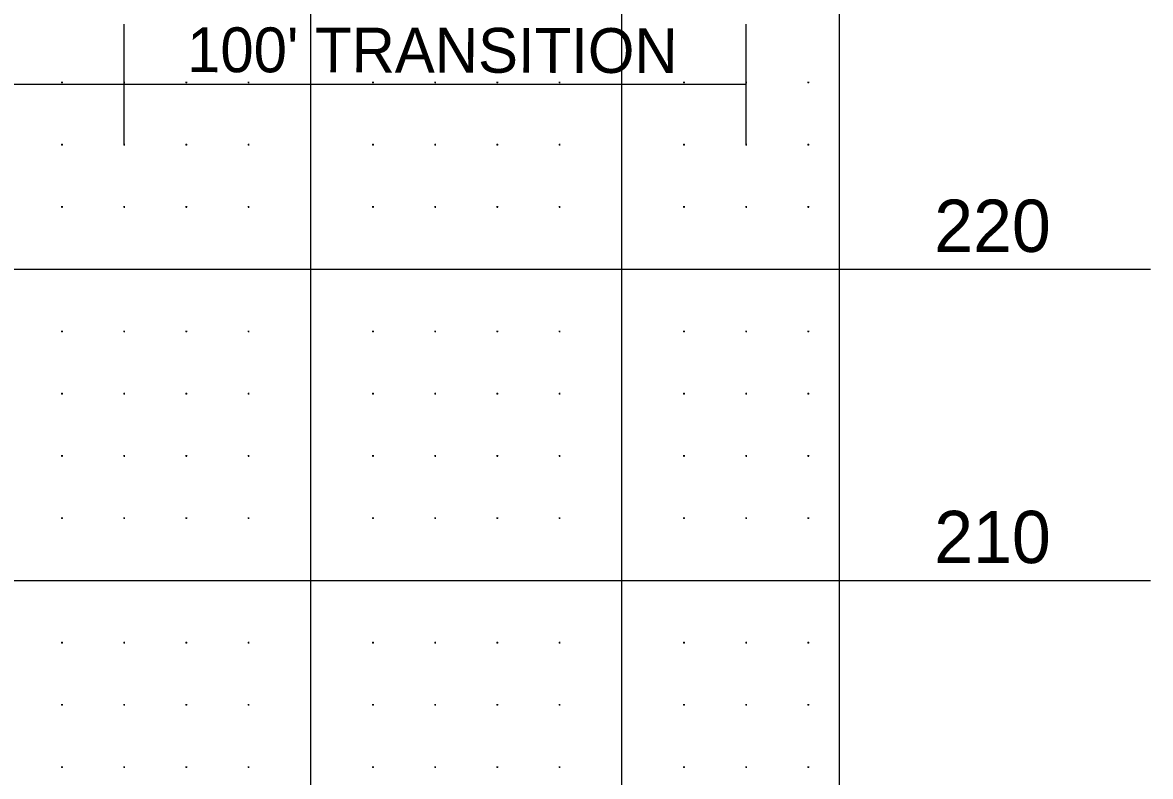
# Model space of a CAD drawing. Extents: x 471 to 2121, y 140 to 650.
# Drawn here: x 1939.7 to 2121.1, y 418.5 to 539.6 of the extents above; entities that cross this region are included whole.
import ezdxf

# ---------------------------------------------------------------- set-up
doc = ezdxf.new("R2010")
doc.units = 0
for name, color, linetype in [('DSN_DRFT_Border Grid', 7, 'Continuous'), ('DSN_RDWY_Prof Annotation', 7, 'Continuous'), ('Transition Dimensions', 7, 'Continuous')]:
    doc.layers.add(name, color=color, linetype=linetype)

msp = doc.modelspace()

# ---------------------------------------------------------------- linework, layer by layer
at = {"layer": 'DSN_DRFT_Border Grid'}
for p, q in [((1986.06, 150), (1986.06, 650)), ((1986.06, 150), (1986.06, 650)), ((2036.06, 150), (2036.06, 650)), ((2036.06, 150), (2036.06, 650)), ((2071.06, 150), (2071.06, 650)), ((2071.06, 150), (2071.06, 650)), ((1946.18, 530), (1945.94, 530)), ((1946.18, 530), (1945.94, 530)), ((1946.06, 530.12), (1946.06, 529.88)), ((1946.06, 530.12), (1946.06, 529.88)), ((1956.18, 530), (1955.94, 530)), ((1956.18, 530), (1955.94, 530)), ((1956.06, 530.12), (1956.06, 529.88)), ((1956.06, 530.12), (1956.06, 529.88)), ((1966.18, 530), (1965.94, 530)), ((1966.18, 530), (1965.94, 530)), ((1966.06, 530.12), (1966.06, 529.88)), ((1966.06, 530.12), (1966.06, 529.88)), ((1976.18, 530), (1975.94, 530)), ((1976.18, 530), (1975.94, 530)), ((1976.06, 530.12), (1976.06, 529.88)), ((1976.06, 530.12), (1976.06, 529.88)), ((1996.18, 530), (1995.94, 530)), ((1996.18, 530), (1995.94, 530)), ((1996.06, 530.12), (1996.06, 529.88)), ((1996.06, 530.12), (1996.06, 529.88)), ((2006.18, 530), (2005.94, 530)), ((2006.18, 530), (2005.94, 530)), ((2006.06, 530.12), (2006.06, 529.88)), ((2006.06, 530.12), (2006.06, 529.88)), ((2016.18, 530), (2015.94, 530)), ((2016.18, 530), (2015.94, 530)), ((2016.06, 530.12), (2016.06, 529.88)), ((2016.06, 530.12), (2016.06, 529.88)), ((2026.18, 530), (2025.94, 530)), ((2026.18, 530), (2025.94, 530)), ((2026.06, 530.12), (2026.06, 529.88)), ((2026.06, 530.12), (2026.06, 529.88)), ((2046.18, 530), (2045.94, 530)), ((2046.18, 530), (2045.94, 530)), ((2046.06, 530.12), (2046.06, 529.88)), ((2046.06, 530.12), (2046.06, 529.88)), ((2056.18, 530), (2055.94, 530)), ((2056.18, 530), (2055.94, 530)), ((2056.06, 530.12), (2056.06, 529.88)), ((2056.06, 530.12), (2056.06, 529.88)), ((2066.18, 530), (2065.94, 530)), ((2066.18, 530), (2065.94, 530)), ((2066.06, 530.12), (2066.06, 529.88)), ((2066.06, 530.12), (2066.06, 529.88)), ((1946.18, 520), (1945.94, 520)), ((1946.18, 520), (1945.94, 520)), ((1946.06, 520.12), (1946.06, 519.88)), ((1946.06, 520.12), (1946.06, 519.88)), ((1956.18, 520), (1955.94, 520)), ((1956.18, 520), (1955.94, 520)), ((1956.06, 520.12), (1956.06, 519.88)), ((1956.06, 520.12), (1956.06, 519.88)), ((1966.18, 520), (1965.94, 520)), ((1966.18, 520), (1965.94, 520)), ((1966.06, 520.12), (1966.06, 519.88)), ((1966.06, 520.12), (1966.06, 519.88)), ((1976.18, 520), (1975.94, 520)), ((1976.18, 520), (1975.94, 520)), ((1976.06, 520.12), (1976.06, 519.88)), ((1976.06, 520.12), (1976.06, 519.88)), ((1996.18, 520), (1995.94, 520)), ((1996.18, 520), (1995.94, 520)), ((1996.06, 520.12), (1996.06, 519.88)), ((1996.06, 520.12), (1996.06, 519.88)), ((2006.18, 520), (2005.94, 520)), ((2006.18, 520), (2005.94, 520)), ((2006.06, 520.12), (2006.06, 519.88)), ((2006.06, 520.12), (2006.06, 519.88)), ((2016.18, 520), (2015.94, 520)), ((2016.18, 520), (2015.94, 520)), ((2016.06, 520.12), (2016.06, 519.88)), ((2016.06, 520.12), (2016.06, 519.88)), ((2026.18, 520), (2025.94, 520)), ((2026.18, 520), (2025.94, 520)), ((2026.06, 520.12), (2026.06, 519.88)), ((2026.06, 520.12), (2026.06, 519.88)), ((2046.18, 520), (2045.94, 520)), ((2046.18, 520), (2045.94, 520)), ((2046.06, 520.12), (2046.06, 519.88)), ((2046.06, 520.12), (2046.06, 519.88)), ((2056.18, 520), (2055.94, 520)), ((2056.18, 520), (2055.94, 520)), ((2056.06, 520.12), (2056.06, 519.88)), ((2056.06, 520.12), (2056.06, 519.88)), ((2066.18, 520), (2065.94, 520)), ((2066.18, 520), (2065.94, 520)), ((2066.06, 520.12), (2066.06, 519.88)), ((2066.06, 520.12), (2066.06, 519.88)), ((1946.18, 510), (1945.94, 510)), ((1946.18, 510), (1945.94, 510)), ((1946.06, 510.12), (1946.06, 509.88)), ((1946.06, 510.12), (1946.06, 509.88)), ((1956.18, 510), (1955.94, 510)), ((1956.18, 510), (1955.94, 510)), ((1956.06, 510.12), (1956.06, 509.88)), ((1956.06, 510.12), (1956.06, 509.88)), ((1966.18, 510), (1965.94, 510)), ((1966.18, 510), (1965.94, 510)), ((1966.06, 510.12), (1966.06, 509.88)), ((1966.06, 510.12), (1966.06, 509.88)), ((1976.18, 510), (1975.94, 510)), ((1976.18, 510), (1975.94, 510)), ((1976.06, 510.12), (1976.06, 509.88)), ((1976.06, 510.12), (1976.06, 509.88)), ((1996.18, 510), (1995.94, 510)), ((1996.18, 510), (1995.94, 510)), ((1996.06, 510.12), (1996.06, 509.88)), ((1996.06, 510.12), (1996.06, 509.88)), ((2006.18, 510), (2005.94, 510)), ((2006.18, 510), (2005.94, 510)), ((2006.06, 510.12), (2006.06, 509.88)), ((2006.06, 510.12), (2006.06, 509.88)), ((2016.18, 510), (2015.94, 510)), ((2016.18, 510), (2015.94, 510)), ((2016.06, 510.12), (2016.06, 509.88)), ((2016.06, 510.12), (2016.06, 509.88)), ((2026.18, 510), (2025.94, 510)), ((2026.18, 510), (2025.94, 510)), ((2026.06, 510.12), (2026.06, 509.88)), ((2026.06, 510.12), (2026.06, 509.88)), ((2046.18, 510), (2045.94, 510)), ((2046.18, 510), (2045.94, 510)), ((2046.06, 510.12), (2046.06, 509.88)), ((2046.06, 510.12), (2046.06, 509.88)), ((2056.18, 510), (2055.94, 510)), ((2056.18, 510), (2055.94, 510)), ((2056.06, 510.12), (2056.06, 509.88)), ((2056.06, 510.12), (2056.06, 509.88)), ((2066.18, 510), (2065.94, 510)), ((2066.18, 510), (2065.94, 510)), ((2066.06, 510.12), (2066.06, 509.88)), ((2066.06, 510.12), (2066.06, 509.88)), ((521.06, 500), (2071.06, 500)), ((521.06, 500), (2071.06, 500)), ((2071.06, 500), (2121.06, 500)), ((1946.18, 490), (1945.94, 490)), ((1946.18, 490), (1945.94, 490)), ((1946.06, 490.12), (1946.06, 489.88)), ((1946.06, 490.12), (1946.06, 489.88)), ((1956.18, 490), (1955.94, 490)), ((1956.18, 490), (1955.94, 490)), ((1956.06, 490.12), (1956.06, 489.88)), ((1956.06, 490.12), (1956.06, 489.88)), ((1966.18, 490), (1965.94, 490)), ((1966.18, 490), (1965.94, 490)), ((1966.06, 490.12), (1966.06, 489.88)), ((1966.06, 490.12), (1966.06, 489.88)), ((1976.18, 490), (1975.94, 490)), ((1976.18, 490), (1975.94, 490)), ((1976.06, 490.12), (1976.06, 489.88)), ((1976.06, 490.12), (1976.06, 489.88)), ((1996.18, 490), (1995.94, 490)), ((1996.18, 490), (1995.94, 490)), ((1996.06, 490.12), (1996.06, 489.88)), ((1996.06, 490.12), (1996.06, 489.88)), ((2006.18, 490), (2005.94, 490)), ((2006.18, 490), (2005.94, 490)), ((2006.06, 490.12), (2006.06, 489.88)), ((2006.06, 490.12), (2006.06, 489.88)), ((2016.18, 490), (2015.94, 490)), ((2016.18, 490), (2015.94, 490)), ((2016.06, 490.12), (2016.06, 489.88)), ((2016.06, 490.12), (2016.06, 489.88)), ((2026.18, 490), (2025.94, 490)), ((2026.18, 490), (2025.94, 490)), ((2026.06, 490.12), (2026.06, 489.88)), ((2026.06, 490.12), (2026.06, 489.88)), ((2046.18, 490), (2045.94, 490)), ((2046.18, 490), (2045.94, 490)), ((2046.06, 490.12), (2046.06, 489.88)), ((2046.06, 490.12), (2046.06, 489.88)), ((2056.18, 490), (2055.94, 490)), ((2056.18, 490), (2055.94, 490)), ((2056.06, 490.12), (2056.06, 489.88)), ((2056.06, 490.12), (2056.06, 489.88)), ((2066.18, 490), (2065.94, 490)), ((2066.18, 490), (2065.94, 490)), ((2066.06, 490.12), (2066.06, 489.88)), ((2066.06, 490.12), (2066.06, 489.88)), ((1946.18, 480), (1945.94, 480)), ((1946.18, 480), (1945.94, 480)), ((1946.06, 480.12), (1946.06, 479.88)), ((1946.06, 480.12), (1946.06, 479.88)), ((1956.18, 480), (1955.94, 480)), ((1956.18, 480), (1955.94, 480)), ((1956.06, 480.12), (1956.06, 479.88)), ((1956.06, 480.12), (1956.06, 479.88)), ((1966.18, 480), (1965.94, 480)), ((1966.18, 480), (1965.94, 480)), ((1966.06, 480.12), (1966.06, 479.88)), ((1966.06, 480.12), (1966.06, 479.88)), ((1976.18, 480), (1975.94, 480)), ((1976.18, 480), (1975.94, 480)), ((1976.06, 480.12), (1976.06, 479.88)), ((1976.06, 480.12), (1976.06, 479.88)), ((1996.18, 480), (1995.94, 480)), ((1996.18, 480), (1995.94, 480)), ((1996.06, 480.12), (1996.06, 479.88)), ((1996.06, 480.12), (1996.06, 479.88)), ((2006.18, 480), (2005.94, 480)), ((2006.18, 480), (2005.94, 480)), ((2006.06, 480.12), (2006.06, 479.88)), ((2006.06, 480.12), (2006.06, 479.88)), ((2016.18, 480), (2015.94, 480)), ((2016.18, 480), (2015.94, 480)), ((2016.06, 480.12), (2016.06, 479.88)), ((2016.06, 480.12), (2016.06, 479.88)), ((2026.18, 480), (2025.94, 480)), ((2026.18, 480), (2025.94, 480)), ((2026.06, 480.12), (2026.06, 479.88)), ((2026.06, 480.12), (2026.06, 479.88)), ((2046.18, 480), (2045.94, 480)), ((2046.18, 480), (2045.94, 480)), ((2046.06, 480.12), (2046.06, 479.88)), ((2046.06, 480.12), (2046.06, 479.88)), ((2056.18, 480), (2055.94, 480)), ((2056.18, 480), (2055.94, 480)), ((2056.06, 480.12), (2056.06, 479.88)), ((2056.06, 480.12), (2056.06, 479.88)), ((2066.18, 480), (2065.94, 480)), ((2066.18, 480), (2065.94, 480)), ((2066.06, 480.12), (2066.06, 479.88)), ((2066.06, 480.12), (2066.06, 479.88)), ((1946.18, 470), (1945.94, 470)), ((1946.18, 470), (1945.94, 470)), ((1946.06, 470.12), (1946.06, 469.88)), ((1946.06, 470.12), (1946.06, 469.88)), ((1956.18, 470), (1955.94, 470)), ((1956.18, 470), (1955.94, 470)), ((1956.06, 470.12), (1956.06, 469.88)), ((1956.06, 470.12), (1956.06, 469.88)), ((1966.18, 470), (1965.94, 470)), ((1966.18, 470), (1965.94, 470)), ((1966.06, 470.12), (1966.06, 469.88)), ((1966.06, 470.12), (1966.06, 469.88)), ((1976.18, 470), (1975.94, 470)), ((1976.18, 470), (1975.94, 470)), ((1976.06, 470.12), (1976.06, 469.88)), ((1976.06, 470.12), (1976.06, 469.88)), ((1996.18, 470), (1995.94, 470)), ((1996.18, 470), (1995.94, 470)), ((1996.06, 470.12), (1996.06, 469.88)), ((1996.06, 470.12), (1996.06, 469.88)), ((2006.18, 470), (2005.94, 470)), ((2006.18, 470), (2005.94, 470)), ((2006.06, 470.12), (2006.06, 469.88)), ((2006.06, 470.12), (2006.06, 469.88)), ((2016.18, 470), (2015.94, 470)), ((2016.18, 470), (2015.94, 470)), ((2016.06, 470.12), (2016.06, 469.88)), ((2016.06, 470.12), (2016.06, 469.88)), ((2026.18, 470), (2025.94, 470)), ((2026.18, 470), (2025.94, 470)), ((2026.06, 470.12), (2026.06, 469.88)), ((2026.06, 470.12), (2026.06, 469.88)), ((2046.18, 470), (2045.94, 470)), ((2046.18, 470), (2045.94, 470)), ((2046.06, 470.12), (2046.06, 469.88)), ((2046.06, 470.12), (2046.06, 469.88)), ((2056.18, 470), (2055.94, 470)), ((2056.18, 470), (2055.94, 470)), ((2056.06, 470.12), (2056.06, 469.88)), ((2056.06, 470.12), (2056.06, 469.88)), ((2066.18, 470), (2065.94, 470)), ((2066.18, 470), (2065.94, 470)), ((2066.06, 470.12), (2066.06, 469.88)), ((2066.06, 470.12), (2066.06, 469.88)), ((1946.18, 460), (1945.94, 460)), ((1946.18, 460), (1945.94, 460)), ((1946.06, 460.12), (1946.06, 459.88)), ((1946.06, 460.12), (1946.06, 459.88)), ((1956.18, 460), (1955.94, 460)), ((1956.18, 460), (1955.94, 460)), ((1956.06, 460.12), (1956.06, 459.88)), ((1956.06, 460.12), (1956.06, 459.88)), ((1966.18, 460), (1965.94, 460)), ((1966.18, 460), (1965.94, 460)), ((1966.06, 460.12), (1966.06, 459.88)), ((1966.06, 460.12), (1966.06, 459.88)), ((1976.18, 460), (1975.94, 460)), ((1976.18, 460), (1975.94, 460)), ((1976.06, 460.12), (1976.06, 459.88)), ((1976.06, 460.12), (1976.06, 459.88)), ((1996.18, 460), (1995.94, 460)), ((1996.18, 460), (1995.94, 460)), ((1996.06, 460.12), (1996.06, 459.88)), ((1996.06, 460.12), (1996.06, 459.88)), ((2006.18, 460), (2005.94, 460)), ((2006.18, 460), (2005.94, 460)), ((2006.06, 460.12), (2006.06, 459.88)), ((2006.06, 460.12), (2006.06, 459.88)), ((2016.18, 460), (2015.94, 460)), ((2016.18, 460), (2015.94, 460)), ((2016.06, 460.12), (2016.06, 459.88)), ((2016.06, 460.12), (2016.06, 459.88)), ((2026.18, 460), (2025.94, 460)), ((2026.18, 460), (2025.94, 460)), ((2026.06, 460.12), (2026.06, 459.88)), ((2026.06, 460.12), (2026.06, 459.88)), ((2046.18, 460), (2045.94, 460)), ((2046.18, 460), (2045.94, 460)), ((2046.06, 460.12), (2046.06, 459.88)), ((2046.06, 460.12), (2046.06, 459.88)), ((2056.18, 460), (2055.94, 460)), ((2056.18, 460), (2055.94, 460)), ((2056.06, 460.12), (2056.06, 459.88)), ((2056.06, 460.12), (2056.06, 459.88)), ((2066.18, 460), (2065.94, 460)), ((2066.18, 460), (2065.94, 460)), ((2066.06, 460.12), (2066.06, 459.88)), ((2066.06, 460.12), (2066.06, 459.88)), ((521.06, 450), (2071.06, 450)), ((521.06, 450), (2071.06, 450)), ((2071.06, 450), (2121.06, 450)), ((1946.18, 440), (1945.94, 440)), ((1946.18, 440), (1945.94, 440)), ((1946.06, 440.12), (1946.06, 439.88)), ((1946.06, 440.12), (1946.06, 439.88)), ((1956.18, 440), (1955.94, 440)), ((1956.18, 440), (1955.94, 440)), ((1956.06, 440.12), (1956.06, 439.88)), ((1956.06, 440.12), (1956.06, 439.88)), ((1966.18, 440), (1965.94, 440)), ((1966.18, 440), (1965.94, 440)), ((1966.06, 440.12), (1966.06, 439.88)), ((1966.06, 440.12), (1966.06, 439.88)), ((1976.18, 440), (1975.94, 440)), ((1976.18, 440), (1975.94, 440)), ((1976.06, 440.12), (1976.06, 439.88)), ((1976.06, 440.12), (1976.06, 439.88)), ((1996.18, 440), (1995.94, 440)), ((1996.18, 440), (1995.94, 440)), ((1996.06, 440.12), (1996.06, 439.88)), ((1996.06, 440.12), (1996.06, 439.88)), ((2006.18, 440), (2005.94, 440)), ((2006.18, 440), (2005.94, 440)), ((2006.06, 440.12), (2006.06, 439.88)), ((2006.06, 440.12), (2006.06, 439.88)), ((2016.18, 440), (2015.94, 440)), ((2016.18, 440), (2015.94, 440)), ((2016.06, 440.12), (2016.06, 439.88)), ((2016.06, 440.12), (2016.06, 439.88)), ((2026.18, 440), (2025.94, 440)), ((2026.18, 440), (2025.94, 440)), ((2026.06, 440.12), (2026.06, 439.88)), ((2026.06, 440.12), (2026.06, 439.88)), ((2046.18, 440), (2045.94, 440)), ((2046.18, 440), (2045.94, 440)), ((2046.06, 440.12), (2046.06, 439.88)), ((2046.06, 440.12), (2046.06, 439.88)), ((2056.18, 440), (2055.94, 440)), ((2056.18, 440), (2055.94, 440)), ((2056.06, 440.12), (2056.06, 439.88)), ((2056.06, 440.12), (2056.06, 439.88)), ((2066.18, 440), (2065.94, 440)), ((2066.18, 440), (2065.94, 440)), ((2066.06, 440.12), (2066.06, 439.88)), ((2066.06, 440.12), (2066.06, 439.88)), ((1946.18, 430), (1945.94, 430)), ((1946.18, 430), (1945.94, 430)), ((1946.06, 430.12), (1946.06, 429.88)), ((1946.06, 430.12), (1946.06, 429.88)), ((1956.18, 430), (1955.94, 430)), ((1956.18, 430), (1955.94, 430)), ((1956.06, 430.12), (1956.06, 429.88)), ((1956.06, 430.12), (1956.06, 429.88)), ((1966.18, 430), (1965.94, 430)), ((1966.18, 430), (1965.94, 430)), ((1966.06, 430.12), (1966.06, 429.88)), ((1966.06, 430.12), (1966.06, 429.88)), ((1976.18, 430), (1975.94, 430)), ((1976.18, 430), (1975.94, 430)), ((1976.06, 430.12), (1976.06, 429.88)), ((1976.06, 430.12), (1976.06, 429.88)), ((1996.18, 430), (1995.94, 430)), ((1996.18, 430), (1995.94, 430)), ((1996.06, 430.12), (1996.06, 429.88)), ((1996.06, 430.12), (1996.06, 429.88)), ((2006.18, 430), (2005.94, 430)), ((2006.18, 430), (2005.94, 430)), ((2006.06, 430.12), (2006.06, 429.88)), ((2006.06, 430.12), (2006.06, 429.88)), ((2016.18, 430), (2015.94, 430)), ((2016.18, 430), (2015.94, 430)), ((2016.06, 430.12), (2016.06, 429.88)), ((2016.06, 430.12), (2016.06, 429.88)), ((2026.18, 430), (2025.94, 430)), ((2026.18, 430), (2025.94, 430)), ((2026.06, 430.12), (2026.06, 429.88)), ((2026.06, 430.12), (2026.06, 429.88)), ((2046.18, 430), (2045.94, 430)), ((2046.18, 430), (2045.94, 430)), ((2046.06, 430.12), (2046.06, 429.88)), ((2046.06, 430.12), (2046.06, 429.88)), ((2056.18, 430), (2055.94, 430)), ((2056.18, 430), (2055.94, 430)), ((2056.06, 430.12), (2056.06, 429.88)), ((2056.06, 430.12), (2056.06, 429.88)), ((2066.18, 430), (2065.94, 430)), ((2066.18, 430), (2065.94, 430)), ((2066.06, 430.12), (2066.06, 429.88)), ((2066.06, 430.12), (2066.06, 429.88)), ((1946.18, 420), (1945.94, 420)), ((1946.18, 420), (1945.94, 420)), ((1946.06, 420.12), (1946.06, 419.88)), ((1946.06, 420.12), (1946.06, 419.88)), ((1956.18, 420), (1955.94, 420)), ((1956.18, 420), (1955.94, 420)), ((1956.06, 420.12), (1956.06, 419.88)), ((1956.06, 420.12), (1956.06, 419.88)), ((1966.18, 420), (1965.94, 420)), ((1966.18, 420), (1965.94, 420)), ((1966.06, 420.12), (1966.06, 419.88)), ((1966.06, 420.12), (1966.06, 419.88)), ((1976.18, 420), (1975.94, 420)), ((1976.18, 420), (1975.94, 420)), ((1976.06, 420.12), (1976.06, 419.88)), ((1976.06, 420.12), (1976.06, 419.88)), ((1996.18, 420), (1995.94, 420)), ((1996.18, 420), (1995.94, 420)), ((1996.06, 420.12), (1996.06, 419.88)), ((1996.06, 420.12), (1996.06, 419.88)), ((2006.18, 420), (2005.94, 420)), ((2006.18, 420), (2005.94, 420)), ((2006.06, 420.12), (2006.06, 419.88)), ((2006.06, 420.12), (2006.06, 419.88)), ((2016.18, 420), (2015.94, 420)), ((2016.18, 420), (2015.94, 420)), ((2016.06, 420.12), (2016.06, 419.88)), ((2016.06, 420.12), (2016.06, 419.88)), ((2026.18, 420), (2025.94, 420)), ((2026.18, 420), (2025.94, 420)), ((2026.06, 420.12), (2026.06, 419.88)), ((2026.06, 420.12), (2026.06, 419.88)), ((2046.18, 420), (2045.94, 420)), ((2046.18, 420), (2045.94, 420)), ((2046.06, 420.12), (2046.06, 419.88)), ((2046.06, 420.12), (2046.06, 419.88)), ((2056.18, 420), (2055.94, 420)), ((2056.18, 420), (2055.94, 420)), ((2056.06, 420.12), (2056.06, 419.88)), ((2056.06, 420.12), (2056.06, 419.88)), ((2066.18, 420), (2065.94, 420)), ((2066.18, 420), (2065.94, 420)), ((2066.06, 420.12), (2066.06, 419.88)), ((2066.06, 420.12), (2066.06, 419.88))]:
    msp.add_line(p, q, dxfattribs=at)
at = {"layer": 'Transition Dimensions'}
for p, q in [((1956.06, 520.12), (1956.06, 539.38)), ((2056.06, 520.12), (2056.06, 539.38)), ((536.06, 529.75), (1956.06, 529.75)), ((1956.06, 529.75), (2056.06, 529.75))]:
    msp.add_line(p, q, dxfattribs=at)

# ---------------------------------------------------------------- texts
at = {"layer": 'DSN_RDWY_Prof Annotation'}
for s, p in [('220', (2086.3, 502.78)), ('220', (2086.3, 502.78)), ('210', (2086.3, 452.78)), ('210', (2086.3, 452.78))]:
    msp.add_text(s, height=8.4, dxfattribs=at).set_placement(p)
at = {"layer": 'Transition Dimensions'}
msp.add_text("100' TRANSITION", height=7.2, rotation=359.8866, dxfattribs=at).set_placement((1966.17, 531.67))

doc.saveas('drawing.dxf')
